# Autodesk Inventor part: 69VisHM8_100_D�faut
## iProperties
Created: 2011-01
Part Number: 69VisHM8_100_D�faut
Document SubType Name: Modeling
Designer: eric
Density: 1 g/cm^3
Mass: 5.79236 g
Surface Area: 30.252 cm^2
Volume: 5.79236 cm^3
Author: eric
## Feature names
1. Base1
